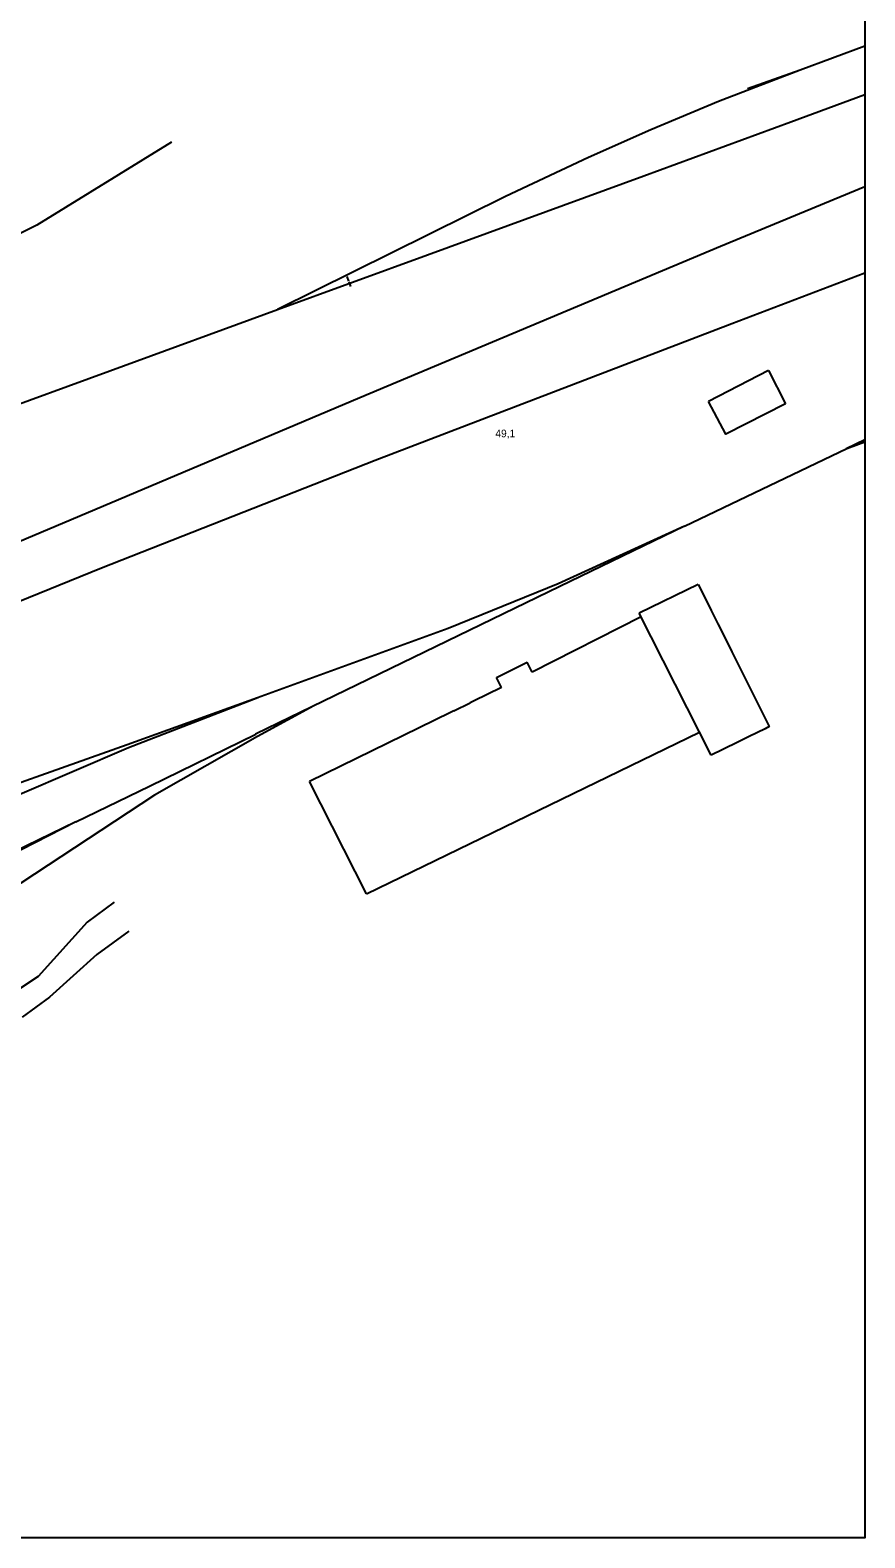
# Model space of a CAD drawing. Extents: x -932963 to -932666, y -737039 to -736000.
# Drawn here: x -932720.9 to -932712.7, y -736961.14 to -736946.3 of the extents above; entities that cross this region are included whole.
import ezdxf

# ---------------------------------------------------------------- set-up
doc = ezdxf.new("R2010")
doc.units = 0
for name, color, linetype in [('Border', 7, 'Continuous'), ('Implicitní', 7, 'Continuous'), ('Koleje_stávající', 7, 'Continuous'), ('Komunikace_stávající', 7, 'Continuous'), ('Objekty_stávající', 7, 'Continuous'), ('SL_05_KOMUNIKACE', 7, 'Continuous')]:
    doc.layers.add(name, color=color, linetype=linetype)

# ---------------------------------------------------------------- blocks, each defined once
blk = doc.blocks.new('5.121_1')
at = {"layer": 'Implicitní'}
blk.add_line((0, 0), (0, 0.0005), dxfattribs=at)
blk = doc.blocks.new('přehledka_1')
at = {"layer": 'Border'}
blk.add_lwpolyline([(0, 0), (0.099915, 0), (0.099915, -0.065218), (0, -0.065218)], close=True, dxfattribs=at)
at = {"layer": 'Koleje_stávající'}
for p, q in [((0.098646, -0.03634), (0.097605, -0.036709)), ((0.096368, -0.045312), (0.099561, -0.043783)), ((0.099551, -0.043788), (0.099915, -0.043611))]:
    blk.add_line(p, q, dxfattribs=at)
for points in [[(0.099915, -0.035871), (0.098646, -0.03634), (0.097038, -0.03696), (0.09571, -0.037516), (0.09448, -0.03806), (0.092852, -0.038824), (0.088366, -0.04105)], [(0.070214, -0.047688), (0.073116, -0.046624), (0.075926, -0.045598), (0.079086, -0.044442), (0.082654, -0.043138), (0.085068, -0.04226), (0.088366, -0.04105), (0.091314, -0.039974), (0.09557, -0.038422), (0.09846, -0.037358), (0.099915, -0.036822)], [(0.034457, -0.065218), (0.036094, -0.06463), (0.042022, -0.062434), (0.046232, -0.060838), (0.053854, -0.05786), (0.057568, -0.05638), (0.066464, -0.052712), (0.072204, -0.050292), (0.078868, -0.04748), (0.08431, -0.045184), (0.089984, -0.04278), (0.097074, -0.039804), (0.099915, -0.038627)], [(0.03708, -0.065218), (0.04231, -0.06328), (0.04657, -0.061666), (0.054136, -0.05872), (0.066806, -0.053566), (0.072606, -0.051164), (0.079336, -0.048394), (0.084902, -0.046136), (0.090286, -0.044012), (0.0973, -0.041326), (0.099915, -0.040329)], [(0.09956, -0.043784), (0.099915, -0.043657)], [(0.096369, -0.045311), (0.09392, -0.046503), (0.087936, -0.049405)], [(0.096368, -0.045311), (0.093888, -0.046448)], [(0.093882, -0.046451), (0.091721, -0.04733), (0.087973, -0.048691)], [(0.087976, -0.04869), (0.085436, -0.049675), (0.0833, -0.050595), (0.07568, -0.054149), (0.069227, -0.057414)], [(0.089083, -0.048849), (0.087974, -0.049455), (0.085947, -0.050608), (0.079133, -0.055094)], [(0.087973, -0.048691), (0.08541, -0.049617), (0.081712, -0.050929)], [(0.084401, -0.051131), (0.085851, -0.050427), (0.087937, -0.049405)], [(0.084401, -0.051131), (0.081958, -0.052321), (0.078416, -0.054033), (0.075967, -0.055229), (0.070542, -0.057871), (0.065749, -0.060528), (0.059036, -0.065218)], [(0.084401, -0.051131), (0.08199, -0.052367), (0.07512, -0.056635), (0.0672, -0.061933)]]:
    blk.add_lwpolyline(points, dxfattribs=at)
at = {"layer": 'Komunikace_stávající'}
for points in [[(0.086278, -0.037758), (0.083634, -0.039394), (0.082248, -0.040084), (0.081559, -0.040377), (0.07832, -0.04125), (0.0753, -0.042404), (0.07175, -0.043768), (0.067214, -0.04551), (0.06388, -0.04677), (0.063028, -0.047065), (0.06121, -0.047734), (0.056748, -0.049352), (0.052088, -0.051014), (0.049772, -0.051898), (0.048486, -0.05233), (0.047346, -0.0527), (0.043028, -0.054132), (0.038862, -0.05539), (0.036736, -0.05607), (0.036645, -0.056105)], [(0.085156, -0.05271), (0.08462, -0.053106), (0.08366, -0.054176), (0.080928, -0.055976)], [(0.085442, -0.053284), (0.08481, -0.053742), (0.083884, -0.054582), (0.083348, -0.054974)]]:
    blk.add_lwpolyline(points, dxfattribs=at)
at = {"layer": 'Objekty_stávající'}
for p, q in [((0.098023, -0.042251), (0.09684, -0.042858)), ((0.098023, -0.042251), (0.098358, -0.042904)), ((0.095514, -0.047099), (0.093372, -0.048183)), ((0.093372, -0.048183), (0.093278, -0.04799)), ((0.092768, -0.048489), (0.09267, -0.048288)), ((0.090116, -0.052546), (0.096662, -0.049367))]:
    blk.add_line(p, q, dxfattribs=at)
for points in [[(0.098358, -0.042904), (0.097184, -0.043506), (0.09684, -0.042858)], [(0.09664, -0.04646), (0.095478, -0.047028)], [(0.09664, -0.04646), (0.096742, -0.046665), (0.096896, -0.046974), (0.097026, -0.047235), (0.09718, -0.047545), (0.0973, -0.047785), (0.09745, -0.048087), (0.098034, -0.049258), (0.097953, -0.049298), (0.097644, -0.049451), (0.097431, -0.049556), (0.097124, -0.049707), (0.096892, -0.049822)], [(0.096892, -0.049822), (0.095478, -0.047028)], [(0.09267, -0.048288), (0.093278, -0.04799)], [(0.092768, -0.048489), (0.09222, -0.048757), (0.092157, -0.048788)], [(0.091835, -0.048945), (0.091767, -0.048978), (0.088998, -0.050334)], [(0.091835, -0.048945), (0.092157, -0.048788)], [(0.090116, -0.052546), (0.088998, -0.050334)]]:
    blk.add_lwpolyline(points, dxfattribs=at)
at = {"layer": 'Koleje_stávající', "xscale": 0.2, "yscale": 0.20000000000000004, "rotation": 19.393445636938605}
for p in [(0.08977, -0.040493), (0.089808, -0.040599)]:
    blk.add_blockref('5.121_1', p, dxfattribs=at)
at = {"layer": 'Koleje_stávající'}
blk.add_text('49,1', height=0.00015, dxfattribs=at).set_placement((0.09265, -0.043564))

msp = doc.modelspace()

# ---------------------------------------------------------------- block references
at = {"layer": 'SL_05_KOMUNIKACE', "xscale": 499.99957, "yscale": 499.99957}
msp.add_blockref('přehledka_1', (-932762.654, -736928.528), dxfattribs=at)

doc.saveas('drawing.dxf')
